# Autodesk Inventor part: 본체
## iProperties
Created: 2015-04
Part Number: 본체
Document SubType Name: Modeling
Designer: elite
Density: 2.71 g/cm^3
Material: 알루미늄-6061
Mass: 1065.84 g
Surface Area: 1083.29 cm^2
Volume: 393.298 cm^3
Author: elite
